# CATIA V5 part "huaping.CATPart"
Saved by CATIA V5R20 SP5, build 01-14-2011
Part number: flower
Material "Water": density 1000 kg/m3
Material "Bottle Green": density 7860 kg/m3, Young's modulus 2e+11 Pa, Poisson ratio 0.266
Material "Light Green": density 7860 kg/m3, Young's modulus 2e+11 Pa, Poisson ratio 0.266
Bounding box of the stored display mesh (mm): x -45.563 to 45.563, y -45.563 to 61.991, z 0 to 139.66
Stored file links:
  E:\180222134\成品\part1.CATPart
  C:\Program Files\Dassault Systemes\B20\intel_a\startup\materials\Catalog.CATMaterial
  C:\Program Files\Dassault Systemes\B20\intel_a\startup\materials\teak_2.jpg
  C:\Program Files\Dassault Systemes\B20\intel_a\startup\materials\cedar.jpg
  C:\Program Files\Dassault Systemes\B20\intel_a\startup\materials\blue_env_512x512.jpg
  C:\Program Files\Dassault Systemes\B20\intel_a\startup\materials\DS_star.jpg
  C:\Program Files\Dassault Systemes\B20\intel_a\startup\materials\brown_fabric_02.jpg
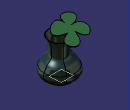
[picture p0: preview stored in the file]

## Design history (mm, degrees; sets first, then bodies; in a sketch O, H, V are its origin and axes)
Body1 (main body), material "Bottle Green"
  Plane1: type Offset, RefPlane xy-plane, Offset 20
  Plane2: type Offset, RefPlane Plane1, Offset 20
  Plane3: type Offset, RefPlane Plane2, Offset 20
  Plane4: type Offset, RefPlane Plane3, Offset 20
  Plane5: type Offset, RefPlane Plane4, Offset 20
  Sketch1 on Plane5, origin (0, 0, 100), H (1, 0, 0), V (0, 1, 0)
    circle A1 centre (0, 0) radius 29.8266
  Sketch2 on Plane4, origin (0, 0, 80), H (1, 0, 0), V (0, 1, 0)
    circle A1 centre (0, 0) radius 23.0726
  Sketch3 on Plane3, origin (0, 0, 60), H (1, 0, 0), V (0, 1, 0)
    circle A1 centre (0, 0) radius 21.9749
  Sketch4 on Plane2, origin (0, 0, 40), H (1, 0, 0), V (0, 1, 0)
    circle A1 centre (0, 0) radius 37.8812
  Sketch5 on Plane1, origin (0, 0, 20), H (1, 0, 0), V (0, 1, 0)
    circle A1 centre (0, 0) radius 45.607
  Sketch6 on xy-plane, origin (0, 0, 0), H (1, 0, 0), V (0, 1, 0)
    circle A1 centre (0, 0) radius 31.6229
  Loft1: solid, Sections (Sketch1; Sketch2; Sketch3; Sketch4; Sketch5; Sketch6)
  Shell1: ExtOffset 0, Face face of Loft1, IntOffset 1
Body2, material "Water"
  Sketch7 on yz-plane, origin (0, 0, 0), H (0, 1, 0), V (0, 0, 1)
    axis line L1 (0, 117.0904) -> (0, -14.88)
    point P1 (0, 117.0904)
    line L2 (0, 0) -> (30.5626, 0)
    line L3 (30.5626, 0) -> (41.5502, 9.897)
    line L4 (41.5502, 9.897) -> (44.4279, 15.6349)
    line L5 (44.4279, 15.6349) -> (44.4279, 21.6335)
    line L6 (44.4279, 21.6335) -> (43.1199, 28.9362)
    line L7 (43.1199, 28.9362) -> (0, 28.9362)
    point P8 (0, 28.9362)
    line L8 (0, 28.9362) -> (0, 0)
    coincidence: P1 V, P8 L1
    vertical: L1 V, L5 V, L8 V
    horizontal: L2 H, L7 H
  Shaft1: profile Sketch7, axis Sketch7.L1, angle 360
Body3, material "Light Green"
  Sketch8 on yz-plane, origin (0, 0, 0), H (0, 1, 0), V (0, 0, 1)
    spline S1 through (4.925, 3.3767) (15.651, 101.1809) (24.5457, 125.9579)
    point P1 (24.5457, 125.9579)
    point P2 (24.5457, 125.9579)
    coincidence: P1 P2
  Plane6: type Normal, Curve Sketch8, RefPoint vertex of Sketch8
  Sketch9 on Plane6, origin (0, -0.2087, 3.0221), H (-1, 0, 0), V (0, 0.9976, 0.0689)
    circle A1 centre (0, 4.9123) radius 1
    point P1 (0, 4.9123)
    radius A1 = 1
    coincidence: P1 V
  Rib1: profile Sketch9, centre curve Sketch8
  Plane7: type OffsetPt, RefPlane zx-plane, RefPoint Sketch8.P2
  Plane8: type Normal, Curve Sketch8, RefPoint Sketch8.P2
  Sketch10 on Plane8, origin (0, 48.2205, 116.1272), H (1, 0, 0), V (0, -0.9235, 0.3835)
    spline S1 through (-4.3423, 41.7545) (-19.2273, 61.1433) (-37.8855, 41.7545) (-12.0228, 30.6751) (-40.4521, 21.5134) (-23.8706, -3.9187) (-8.5786, 13.9217) (2.1878, -12.1777) (28.996, 6.7624) (7.7842, 19.0587) (34.5873, 27.8468) (18.1132, 54.0973) (-4.3423, 41.7545)
    point P1 (-4.3423, 41.7545)
    point P2 (-4.3423, 41.7545)
    coincidence: P1 P2
  Pad1: profile Sketch10, direction (0, -0.3835, -0.9235), length 1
